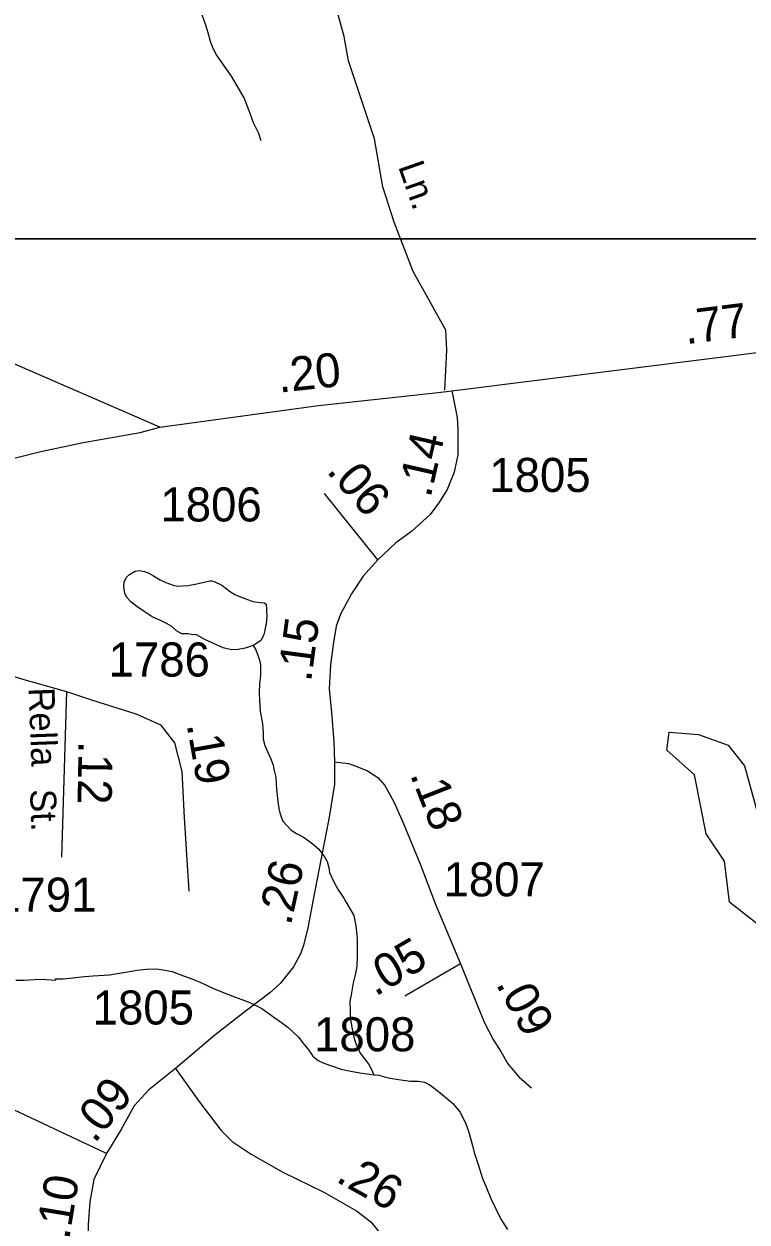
# Model space of a CAD drawing. Extents: x 2126262 to 2293712, y 749403 to 919119.
# Drawn here: x 2186532 to 2189186, y 807445 to 811845 of the extents above; entities that cross this region are included whole.
import ezdxf

# ---------------------------------------------------------------- set-up
doc = ezdxf.new("R2010")
doc.units = 0
for name, color, linetype in [('Exist Hydrographic Misc Water Feature', 7, 'Continuous'), ('Exist Hydrographic Pond Under 1500 Sq Ft', 7, 'Continuous'), ('Exist Road Non-System Type 51', 7, 'Continuous'), ('Exist Road Non-System Type 51 Label', 7, 'Continuous'), ('Exist Road Primary NC Attributed', 7, 'Continuous'), ('Exist Road Primary NC Service Mileage Hundredths English Label', 7, 'Continuous'), ('Exist Road Secondary Mileage Hundredths English Label', 7, 'Continuous'), ('Exist Road Secondary Type 51 Attributed', 7, 'Continuous'), ('Exist Road Secondary Type 51 Label', 7, 'Continuous'), ('Exist Road Secondary Type 51 Number Label', 7, 'Continuous'), ('Map Preparation Inset Cut Line', 7, 'Continuous')]:
    doc.layers.add(name, color=color, linetype=linetype)

msp = doc.modelspace()

# ---------------------------------------------------------------- linework, layer by layer
at = {"layer": 'Exist Hydrographic Misc Water Feature'}
for points in [[(2187402.7, 811415.9), (2187394.5, 811441.8), (2187374.2, 811481.7), (2187358, 811525.6), (2187339.8, 811573.4), (2187311.3, 811623.2), (2187293, 811653), (2187264.7, 811694.9), (2187238.5, 811730.7), (2187224.5, 811756.5), (2187216.3, 811780.5), (2187208.1, 811812.4), (2187199.7, 811840.4), (2187183.5, 811884.2)], [(2187373.6, 809562.3), (2187343.5, 809552), (2187317.6, 809547.9), (2187293.4, 809545.7), (2187263.5, 809553.5), (2187227.6, 809569.3), (2187193.4, 809585), (2187165.3, 809600.8), (2187147.2, 809602.7), (2187133.3, 809604.6), (2187111.4, 809604.5), (2187091.3, 809616.3), (2187075.1, 809632.2), (2187057, 809642), (2187033, 809653.9), (2187002.9, 809667.6), (2186972.7, 809687.5), (2186946.5, 809705.3), (2186924.6, 809723.1), (2186910.6, 809737), (2186902.2, 809753), (2186898.1, 809778.9), (2186899.9, 809794.9), (2186907.9, 809813), (2186919.8, 809823), (2186939.7, 809835.2), (2186955.7, 809837.3), (2186973.8, 809833.4), (2186989.8, 809827.5), (2187007.8, 809817.6), (2187032, 809803.8), (2187052.1, 809793.9), (2187080, 809784.2), (2187096, 809780.3), (2187134.1, 809782.5), (2187166.1, 809788.8), (2187191.9, 809794.9), (2187214.1, 809799.1), (2187221.9, 809799.2), (2187230.1, 809797.2), (2187258, 809783.4), (2187290, 809759.6), (2187306.4, 809749.7), (2187322.4, 809741.9), (2187346.3, 809734), (2187372.4, 809724.2), (2187398.2, 809720.4), (2187414.2, 809718.5), (2187420.6, 809714.5), (2187422.6, 809694.5), (2187422.8, 809668.6), (2187421, 809640.5), (2187418.9, 809632.5), (2187413.2, 809606.5), (2187409.3, 809596.5), (2187401.3, 809580.5), (2187389.6, 809572.3), (2187373.6, 809562.3)], [(2187373.6, 809562.3), (2187383.5, 809546.3), (2187391.9, 809522.4), (2187397.8, 809504.5), (2187400.1, 809488.5), (2187400.3, 809452.5), (2187396.6, 809422.4), (2187394.7, 809388.5), (2187396.8, 809358.5), (2187399, 809320.5), (2187407.5, 809274.6), (2187409.7, 809238.6), (2187409.7, 809218.6), (2187416.1, 809194.6), (2187426.1, 809172.7), (2187436.4, 809148.8), (2187446.6, 809122.9), (2187450.5, 809102.9), (2187456.9, 809079), (2187457.1, 809052.9), (2187459.1, 809035), (2187461.4, 809011), (2187463.2, 808989), (2187467.5, 808963.1), (2187471.8, 808943.1), (2187481.7, 808917.2), (2187512, 808883.4), (2187532.3, 808871.6), (2187558.4, 808857.8), (2187588.5, 808835.9), (2187614.6, 808814.2), (2187634.9, 808786.3), (2187644.7, 808768.4), (2187651.1, 808746.4), (2187653.1, 808728.4), (2187669.3, 808694.6), (2187685.5, 808664.7), (2187695.8, 808648.8), (2187705.8, 808634.8), (2187713.8, 808620.9), (2187742.3, 808571.1), (2187750.5, 808533.1), (2187752.6, 808511.2), (2187754.8, 808487.2), (2187755, 808459.2), (2187755.2, 808421.2), (2187753.6, 808383.2), (2187747.8, 808353.2), (2187739.8, 808323.2), (2187732.3, 808279.1), (2187728.4, 808255.1), (2187728.6, 808223.1), (2187728.8, 808197.2), (2187735.1, 808159.2), (2187739, 808143.2), (2187743.3, 808119.2), (2187749.5, 808101.2), (2187765.5, 808065.4), (2187798.1, 808023.6), (2187806.1, 808007.7), (2187816.3, 807985.7)], [(2186502.4, 808332.6), (2186532.3, 808332.8), (2186570.2, 808335.1), (2186596.1, 808337.3), (2186648.3, 808333.6), (2186647.9, 808337.6), (2186676, 808337.8), (2186700, 808340), (2186754, 808346.4), (2186785.9, 808348.6), (2186846, 808353), (2186882.1, 808359.2), (2186947.7, 808369.7), (2186981.8, 808374), (2187017.9, 808374.2), (2187055.8, 808368.4), (2187075.9, 808364.6), (2187107.9, 808352.8), (2187144, 808339), (2187178, 808325.3), (2187230.3, 808301.6), (2187288.3, 808278), (2187360.5, 808250.6), (2187404.6, 808228.9), (2187438.8, 808205.1), (2187448.9, 808197.2), (2187477, 808177.4), (2187501, 808159.6), (2187539.3, 808123.8), (2187559.6, 808098), (2187577.4, 808076.1), (2187591.8, 808054.2), (2187611.7, 808038.4), (2187632, 808028.5), (2187664, 808016.8), (2187696, 808006.9), (2187732.1, 807999.2), (2187764, 807993.4), (2187800.3, 807987.7), (2187816.3, 807985.7)], [(2187816.3, 807985.7), (2187834.4, 807983.9), (2187868.2, 807974.1), (2187906.3, 807968.4), (2187950.2, 807962.7), (2187978.3, 807962.9), (2188002.3, 807959.1), (2188022.2, 807947.2), (2188046.6, 807929.4), (2188074.5, 807907.6), (2188104.8, 807881.8), (2188132.9, 807848), (2188153.2, 807806.1), (2188163.5, 807778.2), (2188177.8, 807726.4), (2188184, 807700.4), (2188198.3, 807656.5), (2188214.7, 807604.6), (2188226.8, 807576.8), (2188245.3, 807530.9), (2188263.5, 807493), (2188281.8, 807455.1), (2188306, 807417.3)]]:
    msp.add_lwpolyline(points, dxfattribs=at)
at = {"layer": 'Exist Hydrographic Pond Under 1500 Sq Ft'}
msp.add_lwpolyline([(2189463.6, 808382.4), (2189313.7, 808378.9), (2189255.6, 808406.3), (2189245.6, 808521.3), (2189120.7, 808619.1), (2189102.7, 808770.3), (2189035.6, 808870.1), (2188992.6, 809087.5), (2188891.7, 809178.2), (2188899.7, 809243.6), (2189007.5, 809234.8), (2189116.6, 809196.5), (2189175.7, 809119.8), (2189226.5, 808938.4), (2189276.6, 808878.3), (2189368.6, 808840.4), (2189513.6, 808407.6), (2189463.6, 808382.4)], dxfattribs=at)
at = {"layer": 'Exist Road Non-System Type 51'}
msp.add_lwpolyline([(2188076.7, 810500), (2188084.3, 810647.2), (2188080.5, 810720.1), (2187960.7, 810935.2), (2187890.9, 811116.7), (2187849, 811246.9), (2187818.3, 811422.9), (2187759.7, 811598.8), (2187723.5, 811709.6), (2187706.7, 811798.9), (2187628.6, 812083.8), (2187587.1, 812305.8), (2187559.1, 812392.4), (2187584.3, 812601.9), (2187609.3, 812955.3), (2187561.9, 812994.5), (2187500.5, 813025.2)], dxfattribs=at)
at = {"layer": 'Exist Road Primary NC Attributed'}
for points in [[(2188102, 810496.8), (2189350.1, 810654.1), (2189599.2, 810698.1), (2190190.1, 810763), (2191772.4, 810973.9), (2191910.5, 810986.5), (2192074.5, 810987.2), (2192160.1, 810972.4)], [(2187030.9, 810364.1), (2187612.9, 810443.2), (2188051.5, 810490.6), (2188102, 810496.8)], [(2185230.9, 809934), (2185458.4, 809994), (2185964.2, 810116.2), (2186333.3, 810209.1), (2186593.5, 810274), (2186749.8, 810307.6), (2186958.4, 810344.6), (2187030.9, 810364.1)]]:
    msp.add_lwpolyline(points, dxfattribs=at)
at = {"layer": 'Exist Road Secondary Type 51 Attributed'}
msp.add_line((2186687.6, 809392.7), (2186670.1, 808785.2), dxfattribs=at)
for points in [[(2187030.9, 810364.1), (2186462.3, 810610.6), (2185645.4, 810995.4), (2185405.1, 811160.5), (2185150.4, 811415.2), (2185037.7, 811497.2), (2184919.9, 811543.2), (2184665.2, 811588), (2184570.5, 811611.1), (2184183.9, 811879.9), (2183401.8, 812516.1), (2183133.8, 812683.7), (2182832.4, 812865), (2182674.5, 812949.4)], [(2188102, 810496.8), (2188121.6, 810400), (2188124.6, 810355.8), (2188124.6, 810309.4), (2188124.6, 810262.1), (2188110.2, 810199.2), (2188084.5, 810134.4), (2188056.7, 810089.1), (2188022.7, 810043.8), (2187954.7, 809980.9), (2187896.6, 809939.7), (2187830.7, 809876.9)], [(2187830.7, 809876.9), (2187634.8, 810120.2)], [(2187830.7, 809876.9), (2187776.6, 809817.2), (2187733.4, 809751.3), (2187694.2, 809677.2), (2187677.9, 809633.2), (2187668.3, 809573.6), (2187657.2, 809490.8), (2187652, 809403.3), (2187660.2, 809315.7), (2187669, 809208.7), (2187672.1, 809135.5)], [(2186214.2, 809538.8), (2186326.5, 809502.7), (2186523.3, 809439.8), (2186687.6, 809392.7)], [(2186687.6, 809392.7), (2186779.7, 809362.7), (2186945.7, 809309.6), (2187033.6, 809270.5), (2187083.9, 809204.9), (2187111.1, 809099.4), (2187119.4, 808929), (2187137.6, 808660.1)], [(2187672.1, 809135.5), (2187671.1, 809053.2), (2187651.5, 808931.7), (2187598.5, 808655.7), (2187574.3, 808524.9), (2187557.8, 808460.1), (2187546.5, 808430.2), (2187520.7, 808381.8), (2187472.8, 808321), (2187433.7, 808287.1), (2187348.2, 808222.2), (2187231.9, 808131.6), (2187087.7, 808009)], [(2187672.1, 809135.5), (2187722.5, 809129.4), (2187753.4, 809118), (2187792.6, 809101.6), (2187830.7, 809076.8), (2187856.4, 809048), (2187889.4, 808988.3), (2187923.6, 808910.9), (2187987.6, 808757.3), (2188041.4, 808615.2), (2188133.6, 808393.7)], [(2188133.6, 808393.7), (2187929.4, 808274)], [(2188133.6, 808393.7), (2188186.7, 808263.8), (2188222.5, 808176.8), (2188253.9, 808114.7), (2188282.1, 808071.1), (2188307.7, 808026.3), (2188349.9, 807976.4), (2188394.1, 807937.4)], [(2186834.3, 807697.2), (2186474, 807866.8), (2186330.6, 807930.8), (2186235.9, 807992.3), (2186171.9, 808053.7), (2186087.4, 808125.4), (2185982.4, 808232.9)], [(2187087.7, 808009), (2186990.4, 807930.8), (2186935.8, 807872.1), (2186890, 807787.4), (2186834.3, 807697.2)], [(2187087.7, 808009), (2187173.7, 807888.6), (2187255.1, 807781.5), (2187296.2, 807741.3), (2187366.3, 807693.9), (2187481.6, 807628), (2187631.9, 807554.9), (2187751.9, 807485.9), (2187805.4, 807445.8), (2187862.1, 807374.7), (2188080.9, 807080.2)], [(2186834.3, 807697.2), (2186788.6, 807601.3), (2186774.2, 807518.9), (2186768, 807436.5), (2186770.1, 807340.8), (2186768, 807182.2)]]:
    msp.add_lwpolyline(points, dxfattribs=at)
at = {"layer": 'Map Preparation Inset Cut Line'}
for points in [[(2133630.5, 852884.6), (2189691.2, 852884.6), (2189691.2, 811054.9), (2164878.1, 811054.9), (2133665.4, 826054.8)], [(2168450.6, 811054.9), (2189691.2, 811054.9), (2189691.2, 794536.3), (2179257.6, 795892.5)]]:
    msp.add_lwpolyline(points, close=True, dxfattribs=at)

# ---------------------------------------------------------------- texts
at = {"layer": 'Exist Road Non-System Type 51 Label'}
msp.add_text('Ln.', height=95, rotation=289.3565, dxfattribs=at).set_placement((2187904.4, 811321.4))
at = {"layer": 'Exist Road Primary NC Service Mileage Hundredths English Label'}
for s, rotation, p in [('.77', 7.183, (2188961.7, 810668.2)), ('.20', 6.1681, (2187468.8, 810490.5))]:
    msp.add_text(s, height=125, rotation=rotation, dxfattribs=at).set_placement(p)
at = {"layer": 'Exist Road Secondary Mileage Hundredths English Label'}
for s, rotation, p in [('.14', 77.074, (2188023.7, 810101.5)), ('.06', 311.2192, (2187639.2, 810201.1)), ('.15', 82.3662, (2187585.4, 809425.9)), ('.19', 280.0531, (2187128.4, 809272.2)), ('.12', 269.1096, (2186732.3, 809211.7)), ('.18', 291.5, (2187947.6, 809088.4)), ('.26', 77.5754, (2187510.9, 808530.9)), ('.05', 30.1977, (2187820.8, 808271.7)), ('.09', 298.7494, (2188261.9, 808319.4)), ('.09', 50.8948, (2186791.2, 807730.7)), ('.26', 330.8618, (2187672.3, 807596)), ('.10', 80.6573, (2186697.3, 807377.3))]:
    msp.add_text(s, height=125, rotation=rotation, dxfattribs=at).set_placement(p)
at = {"layer": 'Exist Road Secondary Type 51 Label'}
for s, p in [('Rella', (2186548.8, 809406.6)), ('St.', (2186554.1, 809033.4))]:
    msp.add_text(s, height=95, rotation=272.088, dxfattribs=at).set_placement(p)
at = {"layer": 'Exist Road Secondary Type 51 Number Label'}
for s, p in [('1805', (2188239.8, 810126)), ('1806', (2187032.7, 810017.6)), ('1786', (2186842.5, 809448.2)), ('1807', (2188071.6, 808640.9)), ('1791', (2186425.9, 808584.7)), ('1805', (2186784, 808170.3)), ('1808', (2187596.5, 808072))]:
    msp.add_text(s, height=125, dxfattribs=at).set_placement(p)

doc.saveas('drawing.dxf')
